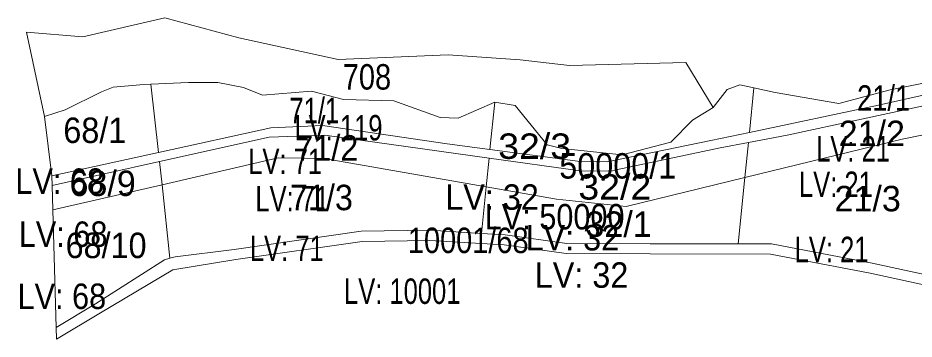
# Model space of a CAD drawing. Extents: x -713758 to -711119, y -1123067 to -1120789.
# Drawn here: x -713758.3 to -713406.4, y -1122257.9 to -1122131.7 of the extents above; entities that cross this region are included whole.
import ezdxf
from ezdxf.enums import TextEntityAlignment as Align

# ---------------------------------------------------------------- set-up
doc = ezdxf.new("R2010")
doc.units = 0
doc.header["$LTSCALE"] = 4
doc.layers.add('10', color=7, linetype='Continuous', lineweight=13)
doc.layers.add('11', color=7, linetype='Continuous')
doc.layers.add('13', color=7, linetype='Continuous')

msp = doc.modelspace()

# ---------------------------------------------------------------- linework, layer by layer
at = {"layer": '10'}
for points in [[(-713754.94, -1122137.33), (-713732.77, -1122139.07), (-713700.57, -1122131.67), (-713671.51, -1122139.56), (-713632.56, -1122147.96), (-713589.38, -1122146.25), (-713561.04, -1122148.13), (-713541.71, -1122150.35), (-713496.06, -1122149.2), (-713485.23, -1122166.91), (-713493.36, -1122171.9), (-713501.95, -1122180.5), (-713521.04, -1122185.54), (-713544.69, -1122183.07), (-713550.48, -1122181.51), (-713563, -1122166.09), (-713571.07, -1122164.74), (-713585.4, -1122171.14), (-713592.45, -1122170.82), (-713610.68, -1122164.26), (-713630.4, -1122163.76), (-713642.95, -1122160.51), (-713662.18, -1122162), (-713669.71, -1122159.06), (-713679.75, -1122157.06), (-713691.32, -1122157.11), (-713706.12, -1122157.75), (-713710.42, -1122157.94), (-713720.82, -1122158.9), (-713725.49, -1122160.79), (-713739.72, -1122167.77), (-713747.85, -1122170.49)], [(-713471.06, -1122176.68), (-713420.3, -1122165.95), (-713396.46, -1122160.64), (-713376.27, -1122156.29), (-713362.5, -1122153.91), (-713349.96, -1122156.15), (-713347.92, -1122146.85), (-713377.62, -1122152.32), (-713415.72, -1122159.97), (-713435.98, -1122165.29), (-713460.95, -1122160.94), (-713469.32, -1122159.14)], [(-713747.85, -1122170.49), (-713744.96, -1122193.77), (-713703.08, -1122184.56), (-713706.12, -1122157.75), (-713710.42, -1122157.94), (-713720.82, -1122158.9), (-713725.49, -1122160.79), (-713739.72, -1122167.77)], [(-713706.12, -1122157.75), (-713703.08, -1122184.56), (-713659.02, -1122174.88), (-713638.64, -1122173.99), (-713589.74, -1122181.2), (-713572.93, -1122183.44), (-713571.07, -1122164.74), (-713585.4, -1122171.14), (-713592.45, -1122170.82), (-713610.68, -1122164.26), (-713630.4, -1122163.76), (-713642.95, -1122160.51), (-713662.18, -1122162), (-713669.71, -1122159.06), (-713679.75, -1122157.06), (-713691.32, -1122157.11)], [(-713572.93, -1122183.44), (-713537.52, -1122188.17), (-713526.89, -1122188.3), (-713486.2, -1122179.88), (-713471.06, -1122176.68), (-713469.32, -1122159.14), (-713474.87, -1122157.95), (-713479.74, -1122159.79), (-713485.23, -1122166.91), (-713493.36, -1122171.9), (-713501.95, -1122180.5), (-713521.04, -1122185.54), (-713544.69, -1122183.07), (-713550.48, -1122181.51), (-713563, -1122166.09), (-713571.07, -1122164.74)], [(-713472.83, -1122194.45), (-713411, -1122179.39), (-713371.73, -1122171.3), (-713368.39, -1122160.09), (-713397.9, -1122165.24), (-713456.26, -1122177.73), (-713471.45, -1122180.61)], [(-713475.42, -1122220.51), (-713462.41, -1122220.52), (-713422.85, -1122228.06), (-713390.72, -1122235.07), (-713371.73, -1122171.3), (-713411, -1122179.39), (-713472.83, -1122194.45)], [(-713702.66, -1122188.17), (-713701.7, -1122197.27), (-713656.07, -1122186.74), (-713638.08, -1122186.96), (-713574.39, -1122198.12), (-713573.26, -1122186.79), (-713637.77, -1122177.83), (-713659.62, -1122178.55)], [(-713574.39, -1122198.12), (-713546.77, -1122202.96), (-713519.48, -1122205.81), (-713472.83, -1122194.45), (-713471.45, -1122180.61), (-713482.5, -1122182.71), (-713523.37, -1122191.42), (-713525.3, -1122191.89), (-713537.5, -1122191.76), (-713573.26, -1122186.79)], [(-713744.84, -1122197.6), (-713744.56, -1122207.17), (-713701.7, -1122197.27), (-713702.66, -1122188.17)], [(-713701.7, -1122197.27), (-713698.65, -1122226.19), (-713696.55, -1122225.62), (-713673.35, -1122222.74), (-713623.48, -1122215.57), (-713596.47, -1122215.18), (-713576.2, -1122216.38), (-713574.39, -1122198.12), (-713638.08, -1122186.96), (-713656.07, -1122186.74)], [(-713576.2, -1122216.38), (-713566.98, -1122216.93), (-713542.74, -1122220.32), (-713510.03, -1122220.47), (-713475.42, -1122220.51), (-713472.83, -1122194.45), (-713519.48, -1122205.81), (-713546.77, -1122202.96), (-713574.39, -1122198.12)], [(-713744.56, -1122207.17), (-713743.22, -1122253.36), (-713727.81, -1122244.09), (-713700.72, -1122226.75), (-713698.65, -1122226.19), (-713701.7, -1122197.27)]]:
    msp.add_lwpolyline(points, close=True, dxfattribs=at)
for points in [[(-713397.9, -1122165.24), (-713456.26, -1122177.73), (-713471.45, -1122180.61), (-713482.5, -1122182.71), (-713523.37, -1122191.42), (-713525.3, -1122191.89), (-713537.5, -1122191.76), (-713573.26, -1122186.79), (-713637.77, -1122177.83), (-713659.62, -1122178.55), (-713702.66, -1122188.17), (-713744.84, -1122197.6), (-713744.96, -1122193.77), (-713703.08, -1122184.56), (-713659.02, -1122174.88), (-713638.64, -1122173.99), (-713589.74, -1122181.2), (-713572.93, -1122183.44), (-713537.52, -1122188.17), (-713526.89, -1122188.3), (-713486.2, -1122179.88), (-713471.06, -1122176.68), (-713420.3, -1122165.95), (-713396.46, -1122160.64)], [(-713390.72, -1122235.07), (-713422.85, -1122228.06), (-713462.41, -1122220.52), (-713475.42, -1122220.51), (-713510.03, -1122220.47), (-713542.74, -1122220.32), (-713566.98, -1122216.93), (-713576.2, -1122216.38), (-713596.47, -1122215.18), (-713623.48, -1122215.57), (-713673.35, -1122222.74), (-713696.55, -1122225.62), (-713698.65, -1122226.19), (-713700.72, -1122226.75), (-713727.81, -1122244.09), (-713743.22, -1122253.36), (-713743.09, -1122257.95), (-713725.89, -1122247.6), (-713697.5, -1122230.75), (-713672.74, -1122226.69), (-713623.17, -1122219.57), (-713596.55, -1122219.18), (-713567.37, -1122220.91), (-713543.02, -1122224.32), (-713510.05, -1122224.47), (-713462.79, -1122224.52), (-713423.67, -1122231.97), (-713375.41, -1122242.51)]]:
    msp.add_lwpolyline(points, dxfattribs=at)

# ---------------------------------------------------------------- texts
at = {"layer": '11'}
for s, width, p in [('708', 0.85, (-713621.22, -1122159.85)), ('21/1', 0.8, (-713418.34, -1122168.16)), ('71/1', 0.75, (-713641.92, -1122173.08)), ('68/1', 0.95, (-713728.09, -1122180.85)), ('71/2', 0.95, (-713637, -1122187.78)), ('32/3', 1.1, (-713555.38, -1122187.1)), ('50000/1', 0.95, (-713522.76, -1122194.84)), ('32/2', 1.1, (-713523.9, -1122203.1)), ('71/3', 0.95, (-713639.11, -1122207.27)), ('68/10', 0.95, (-713723.67, -1122226.11)), ('10001/68', 0.85, (-713581.459, -1122224.12))]:
    msp.add_text(s, height=10, dxfattribs=dict(at, width=width)).set_placement(p, align=Align.CENTER)
for s, p in [('21/2', (-713422.971, -1122182.07)), ('68/9', (-713725.02, -1122201.69)), ('21/3', (-713424.61, -1122207.71)), ('32/1', (-713522.41, -1122217.76))]:
    msp.add_text(s, height=10, dxfattribs=at).set_placement(p, align=Align.CENTER)
at = {"layer": '13'}
for s, width, p in [('LV: 119 ', 0.75, (-713631.024, -1122179.85)), ('LV: 21 ', 0.75, (-713428.946, -1122188.16)), ('LV: 71 ', 0.75, (-713651.959, -1122193.08)), ('LV: 68 ', 0.9, (-713740.203, -1122200.85)), ('LV: 21 ', 0.75, (-713435.686, -1122202.07)), ('LV: 71 ', 0.75, (-713649.147, -1122207.78)), ('LV: 32 ', 0.95, (-713570.339, -1122207.1)), ('LV: 50000 ', 0.9, (-713545.848, -1122214.84)), ('LV: 68 ', 0.9, (-713738.873, -1122221.69)), ('LV: 32 ', 0.95, (-713538.791, -1122223.1)), ('LV: 71 ', 0.75, (-713651.324, -1122227.27)), ('LV: 21 ', 0.75, (-713437.392, -1122227.71)), ('LV: 32 ', 0.95, (-713535.193, -1122237.76)), ('LV: 10001 ', 0.75, (-713605.986, -1122244.12)), ('LV: 68 ', 0.9, (-713739.363, -1122246.11))]:
    msp.add_text(s, height=10, dxfattribs=dict(at, width=width)).set_placement(p, align=Align.CENTER)

doc.saveas('drawing.dxf')
